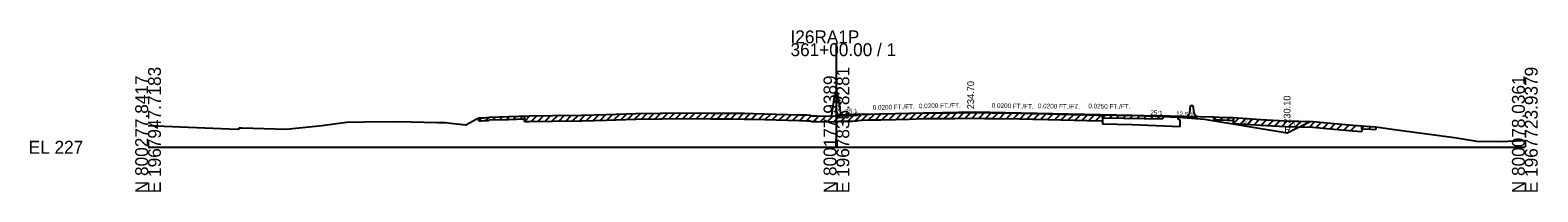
# Model space of a CAD drawing. Extents: x -26 to 304, y -10 to 7527.
# Drawn here: x -25.7 to 302.8, y 5490.3 to 5525.4 of the extents above; entities that cross this region are included whole.
import ezdxf

# ---------------------------------------------------------------- set-up
doc = ezdxf.new("R2010")
doc.units = 0
for name, color, linetype in [('Default', 7, 'Continuous'), ('RD_GPK_XS_Cell', 7, 'Continuous'), ('RD_XS_Base', 7, 'Continuous'), ('RD_XS_Box', 7, 'Continuous'), ('RD_XS_EarthShd', 7, 'Continuous'), ('RD_XS_ExGround', 7, 'Continuous'), ('RD_XS_ExPaveRet', 7, 'Continuous'), ('RD_XS_Misc_Line', 7, 'Continuous'), ('RD_XS_Pave', 7, 'Continuous'), ('RD_XS_PaveShd', 7, 'Continuous'), ('RD_XS_TieSlope', 7, 'Continuous'), ('RD_XS_TX_Elev_EX', 7, 'Continuous'), ('RD_XS_TX_Elev_PR', 7, 'Continuous'), ('RD_XS_TX_Misc', 7, 'Continuous'), ('RD_XS_TX_MkPT', 7, 'Continuous'), ('RD_XS_TX_Profile', 7, 'Continuous'), ('RD_XS_TX_ShdSlope', 7, 'Continuous'), ('RD_XS_TX_Station', 7, 'Continuous')]:
    doc.layers.add(name, color=color, linetype=linetype)

msp = doc.modelspace()

# ---------------------------------------------------------------- linework, layer by layer
at = {"layer": 'Default'}
for p, q in [((226.43, 5506.65), (227.01, 5507.48)), ((226.43, 5506.4), (226.43, 5506.65)), ((228.43, 5506.4), (226.43, 5506.4)), ((227.01, 5507.48), (227.18, 5509.07)), ((227.18, 5509.07), (227.68, 5509.07)), ((227.68, 5509.07), (227.85, 5507.48)), ((227.85, 5507.48), (228.43, 5506.65)), ((228.43, 5506.65), (228.43, 5506.4))]:
    msp.add_line(p, q, dxfattribs=at)
at = {"layer": 'RD_GPK_XS_Cell'}
for p, q in [((150, 5500), (150, 5522.61)), ((0, 5500), (150, 5500)), ((150, 5500), (300, 5500))]:
    msp.add_line(p, q, dxfattribs=at)
at = {"layer": 'RD_XS_Base'}
for p, q in [((150, 5506.86), (150, 5506.98)), ((224.43, 5506), (224.43, 5506.56)), ((208, 5505.08), (214.42, 5504.92)), ((214.42, 5504.92), (224.93, 5504.5)), ((224.93, 5505.98), (224.43, 5506)), ((224.93, 5504.5), (224.93, 5505.98))]:
    msp.add_line(p, q, dxfattribs=at)
at = {"layer": 'RD_XS_Box'}
for p, q in [((226.43, 5506.4), (230.18, 5506.1)), ((230.18, 5506.1), (248.19, 5503.1)), ((248.19, 5503.1), (253.24, 5505.62))]:
    msp.add_line(p, q, dxfattribs=at)
at = {"layer": 'RD_XS_EarthShd'}
for p, q in [((149, 5507), (149.67, 5511.48)), ((150, 5511.48), (149.67, 5511.48)), ((150, 5511.48), (150.33, 5511.48)), ((151, 5507), (150.33, 5511.48)), ((224.43, 5506.56), (226.43, 5506.4))]:
    msp.add_line(p, q, dxfattribs=at)
at = {"layer": 'RD_XS_ExGround'}
msp.add_lwpolyline([(0, 5504.72), (1.73, 5504.68), (17.67, 5504.02), (19.75, 5503.94), (19.85, 5504.24), (20.46, 5504.22), (30.07, 5503.96), (37.84, 5504.75), (43.22, 5505.46), (47.19, 5505.51), (54.48, 5505.58), (62.99, 5505.39), (64.82, 5505.35), (65.89, 5505.24), (69.22, 5504.89), (71.66, 5506.14), (72.1, 5506.36), (72.56, 5506.38), (73.26, 5506.41), (73.74, 5506.43), (74.23, 5506.46), (74.49, 5506.54), (78.53, 5506.69), (83.06, 5506.86), (88.12, 5506.92), (94.53, 5506.99), (99.81, 5507.12), (106.32, 5507.34), (111.63, 5507.42), (112.01, 5507.43), (118.18, 5507.49), (122.6, 5507.43), (123.72, 5507.42), (127.2, 5507.39), (129.94, 5507.37), (131.9, 5507.32), (141.89, 5507.07), (143.53, 5507.01), (144.3, 5506.99), (144.65, 5506.85), (145.8, 5506.83), (148.39, 5506.78), (150, 5506.86), (150.5, 5506.88), (151.1, 5506.9), (151.43, 5506.91), (152.24, 5506.93), (152.83, 5506.89), (153.51, 5506.88), (154.41, 5506.97), (154.59, 5507.07), (155.43, 5507.11), (157.36, 5507.2), (159.67, 5507.24), (162.89, 5507.3), (165.75, 5507.38), (168.96, 5507.48), (173.11, 5507.5), (174.2, 5507.51), (175.82, 5507.51), (180.96, 5507.54), (182.29, 5507.52), (183.96, 5507.49), (189.93, 5507.4), (192.83, 5507.35), (196.03, 5507.28), (204.6, 5507.06), (217.06, 5506.88), (221.11, 5506.82), (222.54, 5506.8), (232.22, 5506.63), (233.43, 5506.56), (235.15, 5506.49), (235.55, 5506.47), (236.42, 5506.44), (242.51, 5506.06), (247.8, 5505.73), (250.41, 5505.69), (253.84, 5505.61), (257.65, 5505.24), (262.52, 5504.79), (266.46, 5504.53), (267.55, 5504.45), (272.13, 5503.79), (284.7, 5502.11), (289.57, 5501.32), (294.41, 5501.23), (300, 5501.44)], dxfattribs=at)
at = {"layer": 'RD_XS_ExPaveRet'}
for p, q in [((72.1, 5505.74), (72.1, 5506.36)), ((82, 5505.57), (82, 5506.82)), ((82, 5506.82), (82, 5506.2)), ((112.01, 5506.18), (118.18, 5506.24)), ((118.18, 5506.24), (122.6, 5506.18)), ((165.75, 5506.13), (168.96, 5506.23)), ((168.96, 5506.23), (173.11, 5506.25)), ((173.11, 5506.25), (174.2, 5506.26)), ((174.2, 5506.26), (175.82, 5506.26)), ((175.82, 5506.26), (180.96, 5506.29)), ((180.96, 5506.29), (182.29, 5506.27)), ((182.29, 5506.27), (183.96, 5506.24)), ((183.96, 5506.24), (189.93, 5506.15)), ((208, 5507.01), (208, 5505.76)), ((208, 5506.39), (208, 5507.01)), ((208, 5506.39), (217.06, 5506.26)), ((217.06, 5506.26), (221.11, 5506.2)), ((221.11, 5506.82), (221.11, 5506.2)), ((232.22, 5506.01), (232.22, 5506.63)), ((236.55, 5505.18), (236.55, 5506.43)), ((236.55, 5506.43), (236.55, 5505.81)), ((72.1, 5505.74), (72.56, 5505.76)), ((72.56, 5505.76), (73.26, 5505.79)), ((73.26, 5505.79), (73.74, 5505.81)), ((73.74, 5505.81), (74.23, 5505.84)), ((74.23, 5505.84), (74.49, 5505.92)), ((74.49, 5505.92), (78.53, 5506.06)), ((78.53, 5506.06), (82, 5506.2)), ((82, 5505.57), (83.06, 5505.61)), ((83.06, 5505.61), (88.12, 5505.67)), ((88.12, 5505.67), (94.53, 5505.74)), ((94.53, 5505.74), (99.81, 5505.87)), ((99.81, 5505.87), (106.32, 5506.09)), ((106.32, 5506.09), (111.63, 5506.17)), ((111.63, 5506.17), (112.01, 5506.18)), ((122.6, 5506.18), (123.72, 5506.17)), ((123.72, 5506.17), (127.2, 5506.14)), ((127.2, 5506.14), (129.94, 5506.12)), ((129.94, 5506.12), (131.9, 5506.07)), ((131.9, 5506.07), (141.89, 5505.82)), ((141.89, 5505.82), (143.53, 5505.76)), ((143.53, 5505.76), (144.3, 5505.74)), ((144.3, 5505.74), (144.65, 5505.6)), ((144.65, 5505.6), (145.8, 5505.58)), ((145.8, 5505.58), (148.39, 5505.53)), ((148.39, 5505.53), (150, 5505.61)), ((150, 5505.61), (150.5, 5505.63)), ((150.5, 5505.63), (151.1, 5505.65)), ((151.1, 5505.65), (151.43, 5505.66)), ((151.43, 5505.66), (152.24, 5505.68)), ((152.24, 5505.68), (152.83, 5505.64)), ((152.83, 5505.64), (153.51, 5505.63)), ((153.51, 5505.63), (154.41, 5505.72)), ((154.41, 5505.72), (154.59, 5505.82)), ((154.59, 5505.82), (155.43, 5505.86)), ((155.43, 5505.86), (157.36, 5505.95)), ((157.36, 5505.95), (159.67, 5505.99)), ((159.67, 5505.99), (162.89, 5506.05)), ((162.89, 5506.05), (165.75, 5506.13)), ((189.93, 5506.15), (192.83, 5506.1)), ((192.83, 5506.1), (196.03, 5506.03)), ((196.03, 5506.03), (204.6, 5505.81)), ((204.6, 5505.81), (208, 5505.76)), ((232.22, 5506.01), (233.43, 5505.94)), ((233.43, 5505.94), (235.15, 5505.86)), ((235.15, 5505.86), (235.55, 5505.85)), ((235.55, 5505.85), (236.42, 5505.81)), ((236.42, 5505.81), (236.55, 5505.81)), ((236.55, 5505.18), (242.51, 5504.81)), ((242.51, 5504.81), (247.8, 5504.48)), ((247.8, 5504.48), (250.41, 5504.44)), ((250.41, 5504.44), (253.84, 5504.36)), ((253.84, 5504.36), (257.65, 5503.99)), ((257.65, 5503.99), (262.52, 5503.54)), ((262.52, 5503.54), (264.46, 5503.41)), ((264.46, 5504.66), (264.46, 5503.41)), ((264.46, 5504.03), (264.46, 5504.66)), ((264.46, 5504.03), (266.46, 5503.9)), ((266.46, 5503.9), (267.55, 5503.82)), ((267.55, 5504.45), (267.55, 5503.82))]:
    msp.add_line(p, q, dxfattribs=at)
at = {"layer": 'RD_XS_Misc_Line'}
for p, q in [((72.1, 5505.74), (72.76, 5506.39)), ((73.6, 5505.8), (74.28, 5506.48)), ((75.1, 5505.94), (75.75, 5506.59)), ((76.6, 5505.99), (77.25, 5506.64)), ((78.1, 5506.05), (78.75, 5506.69)), ((79.6, 5506.1), (80.26, 5506.75)), ((81.1, 5506.16), (81.76, 5506.81)), ((82, 5505.57), (83.29, 5506.87)), ((83.5, 5505.62), (84.76, 5506.88)), ((85, 5505.63), (86.26, 5506.9)), ((86.5, 5505.65), (87.76, 5506.91)), ((88, 5505.66), (89.26, 5506.93)), ((89.5, 5505.68), (90.76, 5506.95)), ((91, 5505.7), (92.26, 5506.96)), ((92.5, 5505.72), (93.76, 5506.98)), ((94, 5505.74), (95.28, 5507.01)), ((95.5, 5505.77), (96.78, 5507.05)), ((97, 5505.8), (98.28, 5507.09)), ((98.5, 5505.84), (99.78, 5507.12)), ((100, 5505.88), (101.29, 5507.17)), ((101.5, 5505.93), (102.79, 5507.22)), ((103, 5505.98), (104.29, 5507.27)), ((104.5, 5506.03), (105.79, 5507.32)), ((106, 5506.08), (107.28, 5507.35)), ((107.5, 5506.1), (108.77, 5507.38)), ((109, 5506.13), (110.27, 5507.4)), ((110.5, 5506.15), (111.77, 5507.42)), ((112, 5506.18), (113.26, 5507.44)), ((113.5, 5506.19), (114.76, 5507.46)), ((115, 5506.21), (116.26, 5507.47)), ((116.5, 5506.23), (117.76, 5507.49)), ((118, 5506.24), (119.24, 5507.48)), ((119.5, 5506.23), (120.73, 5507.46)), ((121, 5506.21), (122.23, 5507.44)), ((122.5, 5506.18), (123.73, 5507.42)), ((124, 5506.16), (125.24, 5507.41)), ((125.5, 5506.15), (126.74, 5507.4)), ((127, 5506.14), (128.24, 5507.39)), ((128.5, 5506.13), (129.74, 5507.38)), ((130, 5506.12), (131.22, 5507.34)), ((131.5, 5506.08), (132.72, 5507.3)), ((133, 5506.05), (134.22, 5507.26)), ((134.5, 5506.01), (135.72, 5507.22)), ((136, 5505.97), (137.22, 5507.19)), ((137.5, 5505.93), (138.72, 5507.15)), ((139, 5505.89), (140.22, 5507.11)), ((140.5, 5505.85), (141.72, 5507.07)), ((142, 5505.81), (143.21, 5507.02)), ((143.5, 5505.77), (144.6, 5506.87)), ((145, 5505.59), (146.23, 5506.82)), ((146.5, 5505.56), (147.73, 5506.79)), ((148, 5505.54), (149.29, 5506.82)), ((149.5, 5505.58), (150.81, 5506.89)), ((151, 5505.65), (152.27, 5506.92)), ((152.5, 5505.66), (153.75, 5506.91)), ((154, 5505.68), (155.43, 5507.11)), ((155.5, 5505.87), (156.81, 5507.18)), ((157, 5505.94), (158.28, 5507.22)), ((158.5, 5505.97), (159.77, 5507.25)), ((160, 5506), (161.27, 5507.27)), ((161.5, 5506.03), (162.77, 5507.3)), ((163, 5506.05), (164.28, 5507.34)), ((164.5, 5506.09), (165.78, 5507.38)), ((166, 5506.13), (167.29, 5507.42)), ((167.5, 5506.18), (168.79, 5507.47)), ((169, 5506.23), (170.26, 5507.48)), ((170.5, 5506.24), (171.76, 5507.49)), ((172, 5506.24), (173.26, 5507.5)), ((173.5, 5506.25), (174.76, 5507.51)), ((175, 5506.26), (176.26, 5507.52)), ((176.5, 5506.27), (177.76, 5507.52)), ((178, 5506.27), (179.26, 5507.53)), ((179.5, 5506.28), (180.76, 5507.53)), ((181, 5506.28), (182.23, 5507.52)), ((182.5, 5506.26), (183.73, 5507.49)), ((184, 5506.24), (185.23, 5507.47)), ((185.5, 5506.21), (186.73, 5507.45)), ((187, 5506.19), (188.23, 5507.42)), ((188.5, 5506.17), (189.73, 5507.4)), ((190, 5506.15), (191.23, 5507.38)), ((191.5, 5506.12), (192.73, 5507.36)), ((193, 5506.1), (194.22, 5507.32)), ((194.5, 5506.06), (195.72, 5507.28)), ((196, 5506.03), (197.22, 5507.25)), ((197.5, 5505.99), (198.72, 5507.21)), ((199, 5505.95), (200.22, 5507.17)), ((200.5, 5505.92), (201.72, 5507.14)), ((202, 5505.88), (203.22, 5507.1)), ((203.5, 5505.84), (204.72, 5507.06)), ((205, 5505.81), (206.23, 5507.04)), ((206.5, 5505.79), (207.73, 5507.02)), ((208, 5506.39), (208.62, 5507)), ((209.5, 5506.37), (210.12, 5506.98)), ((211, 5506.34), (211.62, 5506.96)), ((212.5, 5506.32), (213.12, 5506.94)), ((214, 5506.3), (214.62, 5506.92)), ((215.5, 5506.28), (216.12, 5506.89)), ((217, 5506.26), (217.62, 5506.87)), ((218.5, 5506.24), (219.12, 5506.85)), ((220, 5506.21), (220.62, 5506.83)), ((232.22, 5506.01), (232.82, 5506.6)), ((233.72, 5505.93), (234.32, 5506.52)), ((235.22, 5505.86), (235.83, 5506.46)), ((236.55, 5505.18), (237.72, 5506.36)), ((238.05, 5505.09), (239.22, 5506.26)), ((239.55, 5504.99), (240.72, 5506.17)), ((241.05, 5504.9), (242.22, 5506.08)), ((242.55, 5504.81), (243.72, 5505.98)), ((244.05, 5504.71), (245.22, 5505.89)), ((245.55, 5504.62), (246.72, 5505.8)), ((247.05, 5504.53), (248.24, 5505.73)), ((248.55, 5504.47), (249.78, 5505.7)), ((250.05, 5504.45), (251.27, 5505.67)), ((251.55, 5504.41), (252.77, 5505.63)), ((253.05, 5504.38), (254.24, 5505.57)), ((254.55, 5504.29), (255.69, 5505.43)), ((256.05, 5504.14), (257.19, 5505.29)), ((257.55, 5504), (258.69, 5505.14)), ((259.05, 5503.86), (260.19, 5505)), ((260.55, 5503.72), (261.69, 5504.86)), ((262.05, 5503.58), (263.21, 5504.74)), ((264.46, 5504.03), (265.04, 5504.62)), ((265.96, 5503.94), (266.54, 5504.52))]:
    msp.add_line(p, q, dxfattribs=at)
at = {"layer": 'RD_XS_Pave'}
for p, q in [((156, 5507.22), (180, 5507.7)), ((180, 5507.7), (204, 5507.22)), ((204, 5507.22), (214.42, 5506.96))]:
    msp.add_line(p, q, dxfattribs=at)
at = {"layer": 'RD_XS_PaveShd'}
for p, q in [((156, 5507.22), (150, 5506.98)), ((214.42, 5506.96), (224.43, 5506.56))]:
    msp.add_line(p, q, dxfattribs=at)
at = {"layer": 'RD_XS_TX_Elev_PR'}
for p, q in [((150, 5506.86), (150.5, 5506.88)), ((150.5, 5506.88), (151.1, 5506.9)), ((151.1, 5506.9), (151.43, 5506.91)), ((151.43, 5506.91), (152.24, 5506.93)), ((152.24, 5506.93), (152.83, 5506.89)), ((152.83, 5506.89), (153.51, 5506.88)), ((153.51, 5506.88), (154.41, 5506.97)), ((154.41, 5506.97), (154.59, 5507.07)), ((154.59, 5507.07), (155.43, 5507.11)), ((155.43, 5507.11), (157.36, 5507.2)), ((157.36, 5507.2), (159.67, 5507.24)), ((159.67, 5507.24), (162.89, 5507.3)), ((162.89, 5507.3), (165.75, 5507.38)), ((165.75, 5507.38), (168.96, 5507.48)), ((168.96, 5507.48), (173.11, 5507.5)), ((173.11, 5507.5), (174.2, 5507.51)), ((174.2, 5507.51), (175.82, 5507.51)), ((175.82, 5507.51), (180.96, 5507.54)), ((180.96, 5507.54), (182.29, 5507.52)), ((182.29, 5507.52), (183.96, 5507.49)), ((183.96, 5507.49), (189.93, 5507.4)), ((189.93, 5507.4), (192.83, 5507.35)), ((192.83, 5507.35), (196.03, 5507.28)), ((196.03, 5507.28), (204.6, 5507.06)), ((204.6, 5507.06), (208, 5507.01)), ((208, 5507.01), (208, 5505.08))]:
    msp.add_line(p, q, dxfattribs=at)

# ---------------------------------------------------------------- texts
at = {"layer": 'RD_GPK_XS_Cell'}
for s, p in [('361+00.00 / 1', (140, 5519.81)), ('I26RA1P', (140, 5522.61)), ('EL 227', (-26, 5498.6))]:
    msp.add_text(s, height=2.8, dxfattribs=at).set_placement(p)
for s, p in [('E 1967947.7183', (2.8, 5490)), ('E 1967835.8281', (152.8, 5490)), ('E 1967723.9379', (302.8, 5490)), ('N 800277.8417', (0, 5490)), ('N 800177.9389', (150, 5490)), ('N 800078.0361', (300, 5490))]:
    msp.add_text(s, height=2.8, rotation=90, dxfattribs=at).set_placement(p)
at = {"layer": 'RD_XS_TieSlope'}
msp.add_text('230.10', height=1.5, rotation=90, dxfattribs=at).set_placement((248.94, 5505.1))
at = {"layer": 'RD_XS_TX_Elev_EX'}
msp.add_text('233.86', height=1, rotation=90, dxfattribs=at).set_placement((151, 5506.86))
at = {"layer": 'RD_XS_TX_Misc'}
msp.add_text('12.5:1', height=1, rotation=355.4297, dxfattribs=at).set_placement((223.97, 5506.85))
at = {"layer": 'RD_XS_TX_MkPT'}
for rotation, p in [(2.2906, (151.94, 5507.31)), (357.7112, (218.38, 5507.05))]:
    msp.add_text('25:1', height=1, rotation=rotation, dxfattribs=at).set_placement(p)
at = {"layer": 'RD_XS_TX_Profile'}
for s, rotation, p in [('0.0200 FT./FT.', 1.1458, (167.98, 5508.46)), ('0.0200 FT./FT.', 358.569, (183.84, 5508.6)), ('0.0200 FT./FT.', 358.8542, (193.89, 5508.5)), ('0.0250 FT./FT.', 358.8542, (204.88, 5508.48)), ('0.0200 FT./FT.', 1.1458, (157.92, 5508.15)), ('6:1', 350.5451, (238.57, 5505.21)), ('2:1', 26.5467, (249.65, 5504.39))]:
    msp.add_text(s, height=1, rotation=rotation, dxfattribs=at).set_placement(p)
at = {"layer": 'RD_XS_TX_ShdSlope'}
msp.add_text('R', height=1.5, dxfattribs=at).set_placement((247.6, 5503.1))
at = {"layer": 'RD_XS_TX_Station'}
msp.add_text(' 234.70', height=1.5, rotation=90, dxfattribs=at).set_placement((180, 5507.7))

doc.saveas('drawing.dxf')
